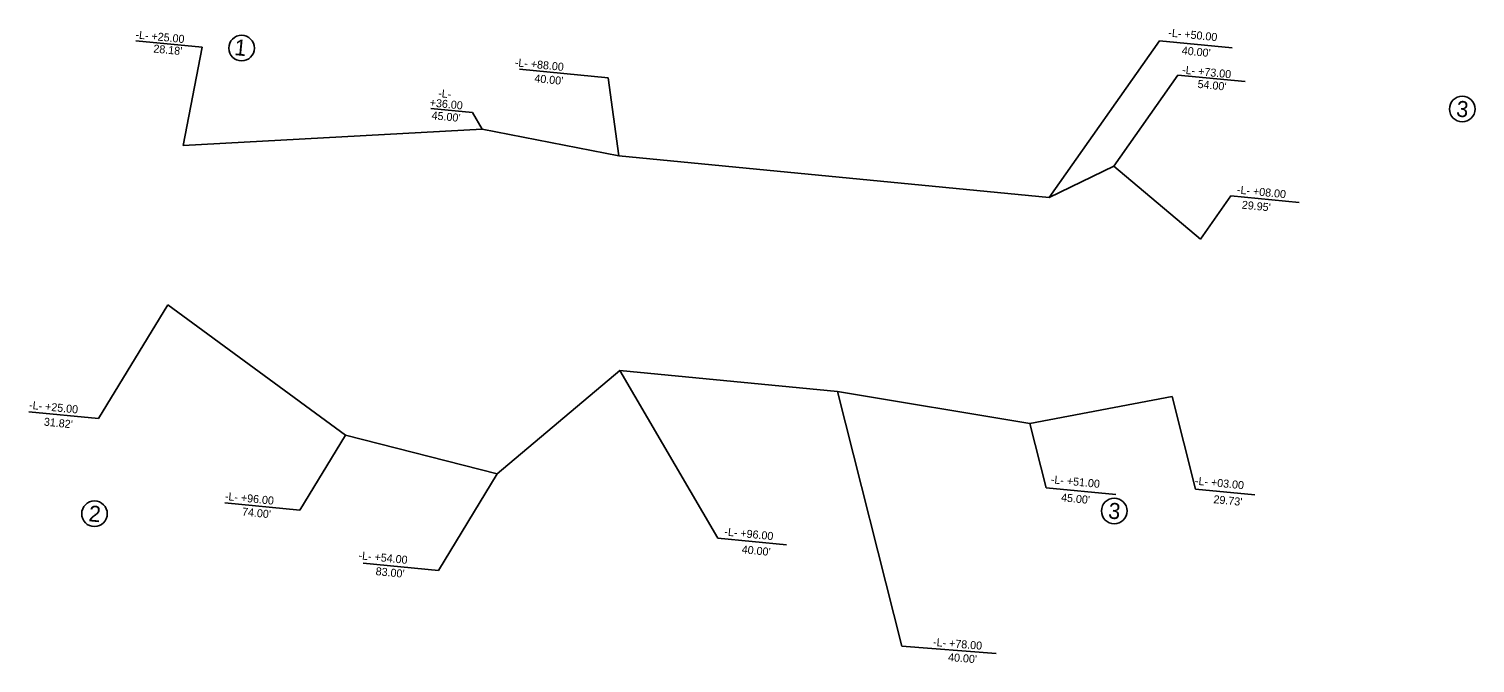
# Model space of a CAD drawing. Extents: x 2061000 to 2061542, y 912555 to 912793.
import ezdxf

# ---------------------------------------------------------------- set-up
doc = ezdxf.new("R2010")
doc.units = 0
for name, color, linetype in [('Prop Easement Construction', 7, 'Continuous'), ('Prop Easement Construction Station Offsets', 7, 'Continuous'), ('Prop Parcel Number CELL', 7, 'Continuous'), ('Prop Parcel Number Text', 7, 'Continuous')]:
    doc.layers.add(name, color=color, linetype=linetype)

msp = doc.modelspace()

# ---------------------------------------------------------------- linework, layer by layer
at = {"layer": 'Prop Easement Construction'}
for p, q in [((2061057.93, 912749.06), (2061170.03, 912755.12)), ((2061170.03, 912755.12), (2061221.31, 912745.14)), ((2061221.31, 912745.14), (2061382.56, 912729.56)), ((2061382.56, 912729.56), (2061406.8, 912741.28)), ((2061406.8, 912741.28), (2061439.32, 912713.98)), ((2061052.15, 912689.34), (2061118.77, 912640.52)), ((2061175.63, 912625.98), (2061221.57, 912664.74)), ((2061221.57, 912664.74), (2061303.19, 912656.85)), ((2061303.19, 912656.85), (2061375.37, 912644.85)), ((2061375.37, 912644.85), (2061428.6, 912655.05)), ((2061118.77, 912640.52), (2061175.63, 912625.98))]:
    msp.add_line(p, q, dxfattribs=at)
at = {"layer": 'Prop Easement Construction Station Offsets'}
for p, q in [((2061065.03, 912785.89), (2061040.18, 912788.29)), ((2061057.93, 912749.06), (2061065.03, 912785.89)), ((2061382.56, 912729.56), (2061423.87, 912788.24)), ((2061423.87, 912788.24), (2061451.21, 912785.6)), ((2061217.31, 912774.38), (2061183.99, 912777.6)), ((2061406.8, 912741.28), (2061430.81, 912775.39)), ((2061430.81, 912775.39), (2061456.08, 912772.95)), ((2061221.31, 912745.14), (2061217.31, 912774.38)), ((2061166.35, 912761.41), (2061150.77, 912762.91)), ((2061170.03, 912755.12), (2061166.35, 912761.41)), ((2061439.32, 912713.98), (2061450.7, 912730.15)), ((2061450.7, 912730.15), (2061476.32, 912727.67)), ((2061052.15, 912689.34), (2061026.25, 912646.71)), ((2061258.34, 912601.9), (2061221.57, 912664.74)), ((2061327.34, 912561.49), (2061303.19, 912656.85)), ((2061437.41, 912620.27), (2061428.6, 912655.05)), ((2061026.25, 912646.71), (2061000.14, 912649.24)), ((2061381.48, 912620.74), (2061375.37, 912644.85)), ((2061118.77, 912640.52), (2061101.7, 912612.44)), ((2061175.63, 912625.98), (2061153.67, 912589.85)), ((2061381.48, 912620.74), (2061407.54, 912618.22)), ((2061437.41, 912620.27), (2061459.6, 912618.12)), ((2061101.7, 912612.44), (2061073.52, 912615.16)), ((2061258.34, 912601.9), (2061284.12, 912599.41)), ((2061153.67, 912589.85), (2061125.37, 912592.59)), ((2061327.34, 912561.49), (2061362.64, 912558.69))]:
    msp.add_line(p, q, dxfattribs=at)
at = {"layer": 'Prop Parcel Number CELL'}
for p, q in [((2061079.86, 912785.51), (2061079.86, 912785.51)), ((2061537.4, 912762.69), (2061537.4, 912762.69)), ((2061024.71, 912611.07), (2061024.71, 912611.07)), ((2061406.95, 912612.11), (2061406.95, 912612.11))]:
    msp.add_line(p, q, dxfattribs=at)
for centre in [(2061079.86, 912785.51), (2061537.4, 912762.69), (2061024.71, 912611.07), (2061406.95, 912612.11)]:
    msp.add_circle(centre, 4.8, dxfattribs=at)

# ---------------------------------------------------------------- texts
at = {"layer": 'Prop Easement Construction Station Offsets'}
for s, rotation, p in [('-L- +25.00', 354.4787, (2061039.98, 912789.15)), ('-L- +50.00', 354.4787, (2061427.12, 912789.87)), ("28.18'", 354.4787, (2061046.68, 912783.9)), ("40.00'", 354.4787, (2061432.15, 912783.2)), ('-L- +88.00', 354.4787, (2061182.16, 912778.71)), ("40.00'", 354.4787, (2061189.49, 912772.77)), ('-L- +73.00', 354.4787, (2061432.3, 912775.96)), ('-L-', 354.4787, (2061153.43, 912767.19)), ("54.00'", 354.4787, (2061438.08, 912770.63)), ('+36.00', 354.4787, (2061150.27, 912763.68)), ("45.00'", 354.4787, (2061150.97, 912758.88)), ('-L- +08.00', 354.4787, (2061452.85, 912731.03)), ("29.95'", 354.4787, (2061454.67, 912725.38)), ('-L- +25.00', 354.4787, (2061000.09, 912650.38)), ("31.82'", 354.4787, (2061005.64, 912644.1)), ('-L- +51.00', 354.4787, (2061383.09, 912622.5)), ('-L- +03.00', 354.4787, (2061437.1, 912621.98)), ('-L- +96.00', 354.4787, (2061073.49, 912616.22)), ("45.00'", 354.4787, (2061386.91, 912615.77)), ("29.73'", 354.4787, (2061444.04, 912615.05)), ("74.00'", 354.4787, (2061079.92, 912610.41)), ('-L- +96.00', 354.4787, (2061260.71, 912602.93)), ('-L- +54.00', 354.4787, (2061123.59, 912594.03)), ("40.00'", 354.4787, (2061267.21, 912596.29)), ("83.00'", 354.4787, (2061130, 912588.1)), ('-L- +78.00', 355.467, (2061338.95, 912561.56)), ("40.00'", 355.467, (2061344.58, 912555.91))]:
    msp.add_text(s, height=3, rotation=rotation, dxfattribs=at).set_placement(p)
at = {"layer": 'Prop Parcel Number Text'}
for s, p in [('1', (2061076.94, 912782.93)), ('3', (2061534.98, 912759.91)), ('2', (2061022.32, 912608.29)), ('3', (2061404.53, 912609.33))]:
    msp.add_text(s, height=6, rotation=354.4787, dxfattribs=at).set_placement(p)

doc.saveas('drawing.dxf')
